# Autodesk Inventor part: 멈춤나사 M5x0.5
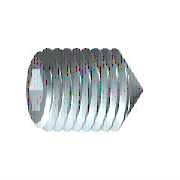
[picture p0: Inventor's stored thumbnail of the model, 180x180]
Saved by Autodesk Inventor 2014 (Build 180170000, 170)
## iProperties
Company: 한국ATC센터
IsCustomPart: 1
Created: 2014-10
Part Number: 멈춤나사 M5x0.5
Material: 강, 연강
Description: 6각 소켓 머리 없는 멈춤 나사
Document SubType Name: Modeling
Standard: KS B 1028
Designer: 한국ATC센터
Standards Organization: KS
Language: ko-KR
Size Designation: 원추점 M5x10
Categories: <MemberInstance><Categories><Category DisplayName="조임쇠" InternalName="e4da775c-781d-43d5-af7c-5136215cf5a6" Mnemonic="FSTN"><Category DisplayName="볼트" InternalN
Density: 7.86 g/cm^3
Mass: 1.16912 g
Surface Area: 1.91683 cm^2
Volume: 0.148743 cm^3
Appearance: 강철
Author: KYOUNG IL JANG
Revision Number: 1
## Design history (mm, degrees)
sketch "스케치1"
  geometry: L1 (0, 0)-(6.167, 0); L2 (10, 1.443)-(10, 2.5); L3 (10, 2.5)-(0, 2.5); L4 (10, 1.443)-(7, 1.443); L5 (7, 1.443)-(6.167, 0); L6 (0, -0.5)-(0, 3) reference; L7 (0, 2.5)-(0, 0)
  constraints: 13 end point, 3 parallel, 1 collinear, 1 perpendicular, 1 point on line
  dimensions: "d0" = 3 distance of L2.start L4.end (= INTI); "d1" = 60 deg angle of L5 L1; "d2" = 5 diameter of L3 L1 (= NND); "d3" = 2.88675 diameter of L4 L1 (= 1.1547 x SW); "d5" = 10 distance from line of L2 L3.end (= NLG)
revolve "본체" sketch "스케치1" stored, may be unused: angle "d6" = 90 deg
sketch "스케치2"
  geometry: L1 (-0.722, 1.25)-(0.722, 1.25); L2 (0.722, 1.25)-(1.443, 0); L3 (1.443, 0)-(0.722, -1.25); L4 (0.722, -1.25)-(-0.722, -1.25); L5 (-0.722, -1.25)-(-1.443, 0); L6 (-1.443, 0)-(-0.722, 1.25); 3 further points
  constraints: 12 end point, 1 coincident, 1 horizontal, 13 other
extrude "슬롯" join sketch "스케치2" taper "d7" = 0 deg; stored distance "d21" = 10
workaxis "Work Axis1"
workplane "Work Plane1"
body "Solid1"
feature "스레드" dims "d12" = 10 (= NLG), "d13" = 0
chamfer "모따기1" distance "d8" = 2.25 (computed from NND, SPD, FAWI); stored, may be unused: angle "d9" = 45 deg (= FAWI), second distance "d34" = 2.25 (computed from NND, SPD, FAWI)
chamfer "모따기2" distance "d10" = 0.49076 (= -0.5 x GD1 + 0.5 x NND); stored, may be unused: angle "d11" = 45 deg (= FAWI), second distance "d35" = 0.49076 (= -0.5 x GD1 + 0.5 x NND)
other parameters: "NND" = 5 [user parameter; used in 5 equation terms], "NLG" = 10 [user parameter; used in 2 equation terms], "INTI" = 3 [user parameter; used in 1 equation term], "FAWI" = 45 deg [user parameter; used in 4 equation terms], "SW" = 2.5 [user parameter; used in 2 equation terms], "GD1" = 4.01848 (= THREADDIA - 1.2269 x PTC) [user parameter; used in 2 equation terms], "d4" = 0, "FAWI1" = 45 deg [user parameter], "SPD" = 0.5 [user parameter; used in 2 equation terms], "d36" = 0, "d37" = 0, "GUL" = 0.49076 (= 0.61345 x PTC) [user parameter], "TPU" = 12.5 (computed from PTC) [user parameter], "TOA" = 30 deg [user parameter], "THREADDIA" = 5 [user parameter; used in 1 equation term], "PTC" = 0.8 [user parameter; used in 4 equation terms], "GAL" = 0.49076 (= 0.61345 x PTC) [user parameter], "E0" = 2.8875 (= 1.155 x SW) [user parameter]
